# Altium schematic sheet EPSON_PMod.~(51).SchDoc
size A4
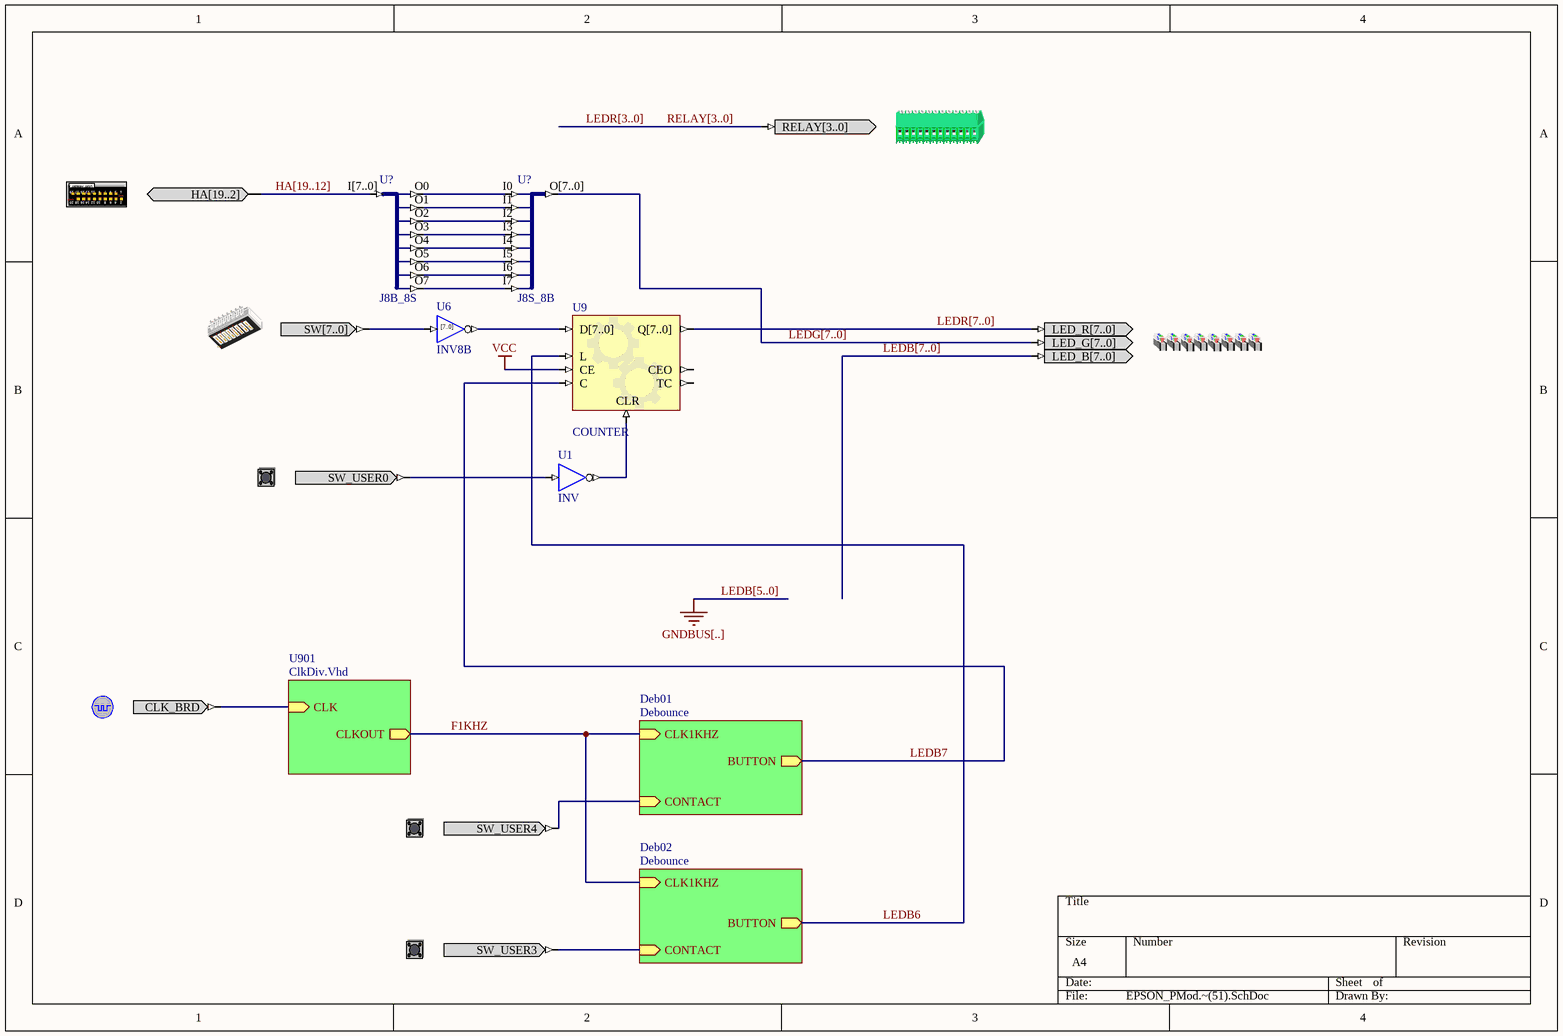
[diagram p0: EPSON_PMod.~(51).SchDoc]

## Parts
(Parts that share a designator on the sheet are numbered #1, #2 ... from top to bottom, then left to right.)
?#1  RELAYCNTR  (value not drawn)
?#2  USER_HEADER_A  (value not drawn)
?#3  DIPSWITCH  (value not drawn)
?#4  LEDS_RGB  (value not drawn)
?#5  USER_BUTTON0  (value not drawn)
?#6  CLOCK_BOARD  (value not drawn)
?#7  USER_BUTTON4  (value not drawn)
?#8  USER_BUTTON3  (value not drawn)
U1  INV
U6  INV8B
U9  COUNTER
U?#1  J8B_8S
U?#2  J8S_8B

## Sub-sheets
Deb01 = Debounce: CONTACT (in), BUTTON (out), CLK1KHZ (in)
Deb02 = Debounce: CONTACT (in), BUTTON (out), CLK1KHZ (in)
U901 = ClkDiv.Vhd: CLK (in), CLKOUT (out)

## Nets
VCC: U9.CE
F1KHZ: sheet U901/CLKOUT, sheet Deb01/CLK1KHZ, sheet Deb02/CLK1KHZ
LEDB6: U9.L ; sheet Deb02/BUTTON
LEDB7: U9.C ; sheet Deb01/BUTTON
Net?#5_SW_USER0: ?#5.SW_USER0 U1.I
Net?#6_CLK_BRD: ?#6.CLK_BRD ; sheet U901/CLK
Net?#7_SW_USER4: ?#7.SW_USER4 ; sheet Deb01/CONTACT
Net?#8_SW_USER3: ?#8.SW_USER3 ; sheet Deb02/CONTACT
NetU1_O: U1.O U9.CLR
NetU?#1_O0: U?#1.O0 U?#2.I0
NetU?#1_O1: U?#1.O1 U?#2.I1
NetU?#1_O2: U?#1.O2 U?#2.I2
NetU?#1_O3: U?#1.O3 U?#2.I3
NetU?#1_O4: U?#1.O4 U?#2.I4
NetU?#1_O5: U?#1.O5 U?#2.I5
NetU?#1_O6: U?#1.O6 U?#2.I6
NetU?#1_O7: U?#1.O7 U?#2.I7

Not connected (* = marked no-connect by the designer): ?#1 RELAY[3..0]; ?#2 HA[19..2]; ?#3 SW[7..0]; ?#4 LED_B[7..0] LED_G[7..0] LED_R[7..0]; U6 I[7..0] O[7..0]; U9 CEO D[7..0] Q[7..0] TC; U?#1 I[7..0]; U?#2 O[7..0]

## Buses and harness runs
bus HA[19..12]
bus LEDB[5..0]
bus LEDB[7..0]
bus LEDG[7..0]
bus LEDR[3..0] = RELAY[3..0]
bus LEDR[7..0]

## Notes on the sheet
- Labels drawn without touching a wire or pin: GNDBUS[..]

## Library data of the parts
?#1 = RELAYCNTR: RELAY; PortComponent: True
?#2 = USER_HEADER_A: User Header A; PortComponent: True
?#3 = DIPSWITCH: 8-Way Dip-Switch; PortComponent: True
?#4 = LEDS_RGB: LEDS RGB; PortComponent: True
?#5 = USER_BUTTON0: Generic User Button; PortComponent: True
?#6 = CLOCK_BOARD: Global System Clock Supply; PortComponent: True
?#7 = USER_BUTTON4: Generic User Button; PortComponent: True
?#8 = USER_BUTTON3: Generic User Button; PortComponent: True
U1 = INV: Inverter; FunctionalClass: Logic Primitive; ArchiveName: GENERIC; VHDLIB_SIM: GENERIC_LIB
U6 = INV8B: 8-Bit Inverter, Bus Version; XilinxEquivalent: INV8; FunctionalClass: Logic Primitive; SubClass: INV; PortSize: 8; ArchiveName: GENERIC; VHDLIB_SIM: GENERIC_LIB
U9 = COUNTER: Configurable Counter; ConfiguratorName: GENERIC_COUNTER; ConfigurationParameters: {}Version[1.0]{}Type[Binary]{}SyncReset[False]{}NegativeClockEdge[False]{}FixedDirection[True]{}IsIncrement[True]{}SignalWidth[8]{}MaxValue[255]{}BusOutput[True]{}Loadable[True]{}BusInput[True]{}
U?#1 = J8B_8S: 8-Bit input bus to 8 single pin outputs; FunctionalClass: Bus Joiner; PortSize: 8; ArchiveName: GENERIC; VHDLIB_SIM: GENERIC_LIB
U?#2 = J8S_8B: 8 Single pin inputs to single 8-Bit output bus; FunctionalClass: Bus Joiner; PortSize: 8; ArchiveName: GENERIC; VHDLIB_SIM: GENERIC_LIB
